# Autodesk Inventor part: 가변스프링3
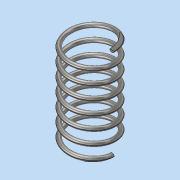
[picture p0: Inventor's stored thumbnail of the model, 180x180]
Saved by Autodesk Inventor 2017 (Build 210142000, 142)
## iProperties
Part Number: 가변스프링3
Material: 스테인레스 스틸
Document SubType Name: Modeling
Designer: MRC
Density: 8 g/cm^3
Appearance: 반연마
Mass: 10.9602 g
Surface Area: 27.6886 cm^2
Volume: 1.37003 cm^3
Author: MRC
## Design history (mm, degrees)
sketch "스케치1"
  geometry: L1 (0, 0)-(10, 0); L2 (10, 0)-(10, 41.411); L3 (10, 41.411)-(0, 41.411); L4 (0, 41.411)-(0, 0); C1 r 1 at (10, 0)
  constraints: 8 end point, 2 parallel, 1 centre point, 1 coincident, 1 horizontal, 1 perpendicular
  dimensions: "d1" = 41.4112 distance of L3.end L1.start (derived); "d2" = 20 diameter of L2 L4; "d3" = 2 diameter of C1
feature "코일1" sketch "스케치1" pitch "d4" = 10; turns "d6" = 7; dims "d5" = 41.4112 (= d1), "d7" = 0, angle "d8" = 90 deg, angle "d9" = 90 deg, "d10" = 0, "d11" = 0
sketch "스케치2"
  geometry: L1 (-20, 41.411)-(20, 41.411); L2 (20, 41.411)-(20, 0); L3 (20, 0)-(-20, 0); L4 (-20, 0)-(-20, 41.411); L5 (0, 41.411)-(0, 0) reference; 2 further points
  constraints: 8 end point, 2 midpoint, 2 parallel, 1 coincident, 1 horizontal, 1 perpendicular
  dimensions: "d12" = 40 distance between parallel lines of L4 L2
extrude "돌출1" sketch "스케치2" stored distance "d13" = 0; taper "d14" = 0 deg
node "솔리드1"
